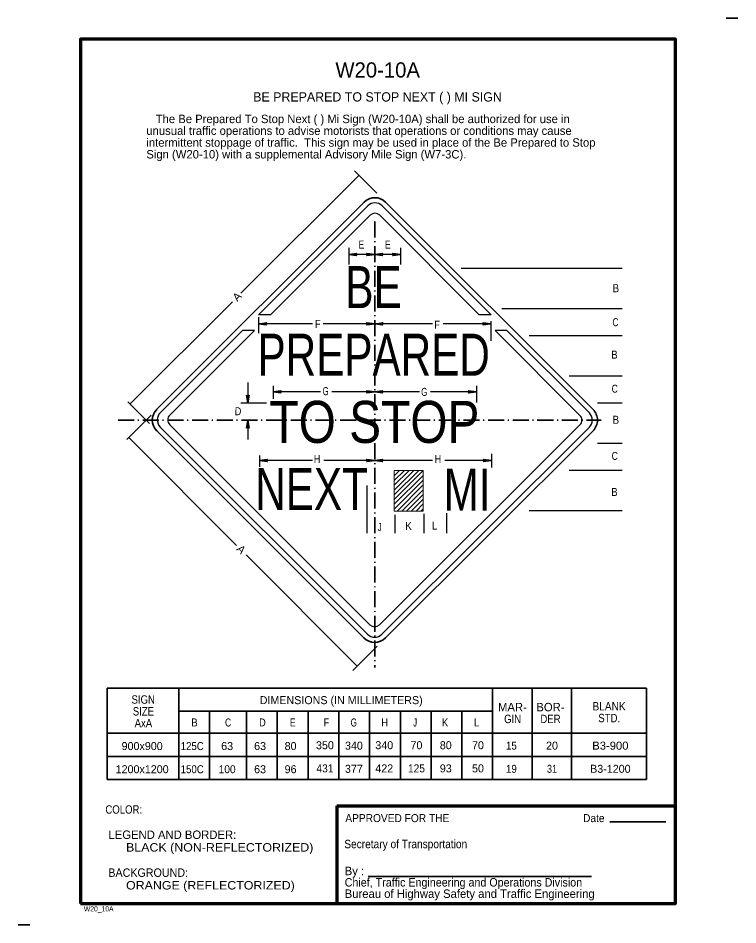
# Model space of a CAD drawing. Extents: x 870593 to 870806, y 249360 to 249629.
import ezdxf
from ezdxf.enums import TextEntityAlignment as Align

# ---------------------------------------------------------------- set-up
doc = ezdxf.new("R2010")
doc.units = 0
doc.header["$LTSCALE"] = 0.95
doc.linetypes.add('DOT_DASHED', pattern=[7.7, 5, -1.2, 0.3, -1.2])
doc.layers.add('1', color=7, linetype='Continuous', lineweight=35)
doc.layers.add('3', color=7, linetype='Continuous', lineweight=25)
doc.layers.add('2', color=7, linetype='Continuous')

msp = doc.modelspace()

# ---------------------------------------------------------------- linework, layer by layer
at = {"layer": '1'}
for p, q in [((870806.1554, 249628.8861), (870802.6554, 249628.8861)), ((870701.6705, 249574.267), (870763.1887, 249512.7487)), ((870633.7721, 249506.4008), (870695.2373, 249444.9356)), ((870768.1554, 249390.3861), (870784.7804, 249390.3861)), ((870696.5304, 249374.1361), (870762.7804, 249374.1361)), ((870596.1554, 249359.7611), (870592.6554, 249359.7611))]:
    msp.add_line(p, q, dxfattribs=at)
at = {"layer": '1', "linetype": 'DOT_DASHED'}
for p, q in [((870698.4193, 249568.5297), (870698.4193, 249436.129)), ((870622.3144, 249509.5669), (870765.6266, 249509.5669))]:
    msp.add_line(p, q, dxfattribs=at)
at = {"layer": '1', "lineweight": 70}
for q in [(870787.6554, 249395.1361), (870687.1554, 249366.1361)]:
    msp.add_line((870687.1554, 249395.1361), q, dxfattribs=at)
msp.add_lwpolyline([(870611.1554, 249366.1361), (870787.6554, 249366.1361), (870787.6554, 249622.6361), (870611.1554, 249622.6361)], close=True, dxfattribs=at)
at = {"layer": '1'}
for centre, start, end in [((870698.4885, 249571.085), 45, 134.93558), ((870760.0068, 249509.5668), 314.93536, 45), ((870698.4193, 249448.1176), 225, 314.93578)]:
    msp.add_arc(centre, 4.5, start, end, dxfattribs=at)
at = {"layer": '3', "lineweight": 35}
for p, q in [((870658.7477, 249547.2164), (870693.7345, 249582.203)), ((870699.0393, 249576.8982), (870692.4095, 249583.528)), ((870633.7721, 249512.8708), (870695.3101, 249574.2706)), ((870656.2165, 249544.6851), (870625.8021, 249514.2707)), ((870631.6121, 249508.5608), (870625.1521, 249515.0207)), ((870632.0821, 249511.0908), (870624.8621, 249503.8708)), ((870701.5976, 249444.932), (870763.1851, 249506.3811)), ((870657.4789, 249472.3499), (870625.4321, 249504.5207)), ((870660.2974, 249469.6239), (870693.2233, 249436.5576)), ((870699.1584, 249442.4928), (870691.9261, 249435.2605)), ((870619.0358, 249430.0185), (870779.0358, 249430.0185)), ((870619.0358, 249430.0185), (870619.0358, 249402.8935)), ((870640.2858, 249430.0185), (870640.2858, 249402.8935)), ((870733.4108, 249430.0185), (870733.4108, 249402.8935)), ((870733.4108, 249430.0185), (870733.4108, 249409.7685)), ((870745.1608, 249430.0185), (870745.1608, 249402.8935)), ((870756.7858, 249430.0185), (870756.7858, 249402.8935)), ((870779.0358, 249430.0185), (870779.0358, 249402.8935)), ((870733.4108, 249423.1435), (870640.2858, 249423.1435)), ((870649.4108, 249423.1435), (870649.4108, 249402.8935)), ((870660.4108, 249423.1435), (870660.4108, 249402.8935)), ((870669.5358, 249423.1435), (870669.5358, 249402.8935)), ((870678.6608, 249423.1435), (870678.6608, 249402.8935)), ((870687.7858, 249423.1435), (870687.7858, 249402.8935)), ((870696.9108, 249423.1435), (870696.9108, 249402.8935)), ((870706.0358, 249423.1435), (870706.0358, 249402.8935)), ((870715.1608, 249423.1435), (870715.1608, 249402.8935)), ((870724.2858, 249423.1435), (870724.2858, 249402.8935)), ((870619.0358, 249416.6435), (870779.0358, 249416.6435)), ((870619.0358, 249409.7685), (870779.0358, 249409.7685)), ((870619.0358, 249409.7685), (870779.0358, 249409.7685)), ((870619.0358, 249402.8935), (870779.0358, 249402.8935))]:
    msp.add_line(p, q, dxfattribs=at)
at = {"layer": '3'}
for p, q in [((870697.0746, 249570.3809), (870667.4804, 249540.8531)), ((870690.7392, 249560.6763), (870690.7392, 249555.7943)), ((870706.0992, 249560.6763), (870706.0992, 249555.7943)), ((870698.4193, 249558.7094), (870690.7392, 249558.7094)), ((870706.0992, 249558.7094), (870698.4193, 249558.7094)), ((870771.8021, 249554.6069), (870724.061, 249554.6069)), ((870771.8021, 249542.6069), (870736.149, 249542.6069)), ((870663.9393, 249540.087), (870663.9393, 249535.4172)), ((870679.9691, 249538.1201), (870663.9393, 249538.1201)), ((870698.4193, 249538.1201), (870683.1316, 249538.1201)), ((870715.5783, 249538.1201), (870698.4193, 249538.1201)), ((870732.8993, 249538.1201), (870718.7593, 249538.1201)), ((870732.8993, 249538.9894), (870732.8993, 249533.0825)), ((870637.6107, 249511.0505), (870662.7484, 249536.1318)), ((870771.8021, 249534.6069), (870744.2076, 249534.6069)), ((870771.8021, 249522.6069), (870756.0835, 249522.6069)), ((870660.7955, 249520.7351), (870660.7955, 249514.6069)), ((870668.2593, 249519.7101), (870668.2593, 249515.8894)), ((870728.5792, 249519.7101), (870728.5792, 249514.8281)), ((870682.3019, 249517.9554), (870668.2593, 249517.9554)), ((870698.4193, 249517.9554), (870685.6764, 249517.9554)), ((870711.761, 249517.9554), (870698.4193, 249517.9554)), ((870728.5792, 249517.9554), (870714.942, 249517.9554)), ((870666.3781, 249514.6069), (870658.7435, 249514.6069)), ((870771.8021, 249514.6069), (870764.5664, 249514.6069)), ((870660.7955, 249509.5669), (870660.7955, 249503.7906)), ((870634.808, 249507.5145), (870696.2979, 249446.0246)), ((870697.006, 249448.8236), (870637.6091, 249508.2205)), ((870759.2969, 249508.1524), (870699.8329, 249448.822)), ((870700.5381, 249446.0223), (870762.0974, 249507.4431)), ((870771.8021, 249502.6069), (870764.5664, 249502.6069)), ((870664.2351, 249499.1209), (870664.2351, 249495.7247)), ((870733.0275, 249499.5455), (870733.0275, 249495.5125)), ((870679.976, 249497.5785), (870664.2351, 249497.5785)), ((870698.4193, 249497.5785), (870683.3438, 249497.5785)), ((870715.5783, 249497.5785), (870698.4193, 249497.5785)), ((870733.0275, 249497.5785), (870719.1834, 249497.5785)), ((870771.8021, 249494.6069), (870756.0835, 249494.6069)), ((870696.0811, 249490.206), (870696.0811, 249475.9846)), ((870712.9684, 249481.735), (870712.9684, 249475.9846)), ((870719.7253, 249481.9474), (870719.7253, 249475.9846)), ((870771.8021, 249482.6069), (870744.2076, 249482.6069)), ((870704.3845, 249481.4166), (870704.3845, 249475.9846))]:
    msp.add_line(p, q, dxfattribs=at)
at = {"layer": '3', "lineweight": 13}
for p, q in [((870704.2325, 249494.4832), (870704.4128, 249494.6635)), ((870704.2325, 249493.069), (870705.827, 249494.6635)), ((870704.2325, 249491.6547), (870707.2412, 249494.6635)), ((870704.2325, 249490.2406), (870708.6554, 249494.6635)), ((870704.2325, 249488.8264), (870710.0696, 249494.6635)), ((870704.2325, 249487.4121), (870711.4839, 249494.6635)), ((870704.2325, 249485.998), (870712.8214, 249494.5869)), ((870704.2325, 249484.5837), (870712.8214, 249493.1726)), ((870704.2325, 249483.1695), (870712.8214, 249491.7584)), ((870705.042, 249482.5648), (870712.8214, 249490.3441)), ((870706.4561, 249482.5648), (870712.8214, 249488.93)), ((870707.8704, 249482.5648), (870712.8214, 249487.5158)), ((870709.2846, 249482.5648), (870712.8214, 249486.1015)), ((870710.6987, 249482.5648), (870712.8214, 249484.6874)), ((870712.113, 249482.5648), (870712.8214, 249483.2731))]:
    msp.add_line(p, q, dxfattribs=at)
at = {"layer": '3'}
for points in [[(870667.4804, 249540.8531), (870663.9694, 249540.8531), (870696.3695, 249573.1805)], [(870700.6098, 249573.1781), (870732.9348, 249540.8531), (870729.4276, 249540.8531), (870699.9015, 249570.3792)], [(870693.0335, 249558.4214), (870692.948, 249558.5875), (870690.7392, 249558.7094), (870693.0335, 249558.4214), (870693.1511, 249558.3208), (870690.7392, 249558.7094), (870692.9463, 249558.8185), (870693.0269, 249558.9829), (870690.7392, 249558.7094), (870693.1511, 249559.0926), (870693.0269, 249558.9829)], [(870696.125, 249558.9974), (870696.2105, 249558.8312), (870698.4193, 249558.7094), (870696.125, 249558.9974), (870696.0074, 249559.098), (870698.4193, 249558.7094), (870696.2122, 249558.6003), (870696.1316, 249558.4359), (870698.4193, 249558.7094), (870696.0074, 249558.3261), (870696.1316, 249558.4359)], [(870700.7135, 249558.4214), (870700.628, 249558.5875), (870698.4193, 249558.7094), (870700.7135, 249558.4214), (870700.8311, 249558.3208), (870698.4193, 249558.7094), (870700.6262, 249558.8185), (870700.7069, 249558.9829), (870698.4193, 249558.7094), (870700.8311, 249559.0926), (870700.7069, 249558.9829)], [(870703.805, 249558.9974), (870703.8905, 249558.8312), (870706.0992, 249558.7094), (870703.805, 249558.9974), (870703.6874, 249559.098), (870706.0992, 249558.7094), (870703.8923, 249558.6003), (870703.8116, 249558.4359), (870706.0992, 249558.7094), (870703.6874, 249558.3261), (870703.8116, 249558.4359)], [(870666.2335, 249537.8321), (870666.148, 249537.9983), (870663.9393, 249538.1201), (870666.2335, 249537.8321), (870666.3511, 249537.7315), (870663.9393, 249538.1201), (870666.1462, 249538.2293), (870666.2269, 249538.3936), (870663.9393, 249538.1201), (870666.3511, 249538.5034), (870666.2269, 249538.3936)], [(870696.125, 249538.4081), (870696.2105, 249538.242), (870698.4193, 249538.1201), (870696.125, 249538.4081), (870696.0074, 249538.5088), (870698.4193, 249538.1201), (870696.2122, 249538.011), (870696.1316, 249537.8466), (870698.4193, 249538.1201), (870696.0074, 249537.7369), (870696.1316, 249537.8466)], [(870700.7135, 249537.8321), (870700.628, 249537.9983), (870698.4193, 249538.1201), (870700.7135, 249537.8321), (870700.8311, 249537.7315), (870698.4193, 249538.1201), (870700.6262, 249538.2293), (870700.7069, 249538.3936), (870698.4193, 249538.1201), (870700.8311, 249538.5034), (870700.7069, 249538.3936)], [(870730.605, 249538.4081), (870730.6905, 249538.242), (870732.8993, 249538.1201), (870730.605, 249538.4081), (870730.4874, 249538.5088), (870732.8993, 249538.1201), (870730.6923, 249538.011), (870730.6116, 249537.8466), (870732.8993, 249538.1201), (870730.4874, 249537.7369), (870730.6116, 249537.8466)], [(870662.7484, 249536.1318), (870659.2375, 249536.1318), (870634.8104, 249511.7595)], [(870762.0998, 249511.6881), (870737.6561, 249536.1318), (870734.149, 249536.1318), (870759.2984, 249510.9824)], [(870661.0835, 249516.9011), (870660.9174, 249516.8156), (870660.7955, 249514.6069), (870661.0835, 249516.9011), (870661.1841, 249517.0187), (870660.7955, 249514.6069), (870660.6864, 249516.8139), (870660.522, 249516.8945), (870660.7955, 249514.6069), (870660.4123, 249517.0187), (870660.522, 249516.8945)], [(870670.5535, 249517.6674), (870670.468, 249517.8335), (870668.2593, 249517.9554), (870670.5535, 249517.6674), (870670.6711, 249517.5667), (870668.2593, 249517.9554), (870670.4663, 249518.0645), (870670.5469, 249518.2289), (870668.2593, 249517.9554), (870670.6711, 249518.3386), (870670.5469, 249518.2289)], [(870696.125, 249518.2434), (870696.2105, 249518.0773), (870698.4193, 249517.9554), (870696.125, 249518.2434), (870696.0074, 249518.344), (870698.4193, 249517.9554), (870696.2122, 249517.8463), (870696.1316, 249517.6819), (870698.4193, 249517.9554), (870696.0074, 249517.5721), (870696.1316, 249517.6819)], [(870700.7135, 249517.6674), (870700.628, 249517.8335), (870698.4193, 249517.9554), (870700.7135, 249517.6674), (870700.8311, 249517.5667), (870698.4193, 249517.9554), (870700.6262, 249518.0645), (870700.7069, 249518.2289), (870698.4193, 249517.9554), (870700.8311, 249518.3386), (870700.7069, 249518.2289)], [(870726.285, 249518.2434), (870726.3705, 249518.0773), (870728.5792, 249517.9554), (870726.285, 249518.2434), (870726.1674, 249518.344), (870728.5792, 249517.9554), (870726.3723, 249517.8463), (870726.2916, 249517.6819), (870728.5792, 249517.9554), (870726.1674, 249517.5721), (870726.2916, 249517.6819)], [(870660.5075, 249507.2726), (870660.6736, 249507.3581), (870660.7955, 249509.5669), (870660.5075, 249507.2726), (870660.4069, 249507.155), (870660.7955, 249509.5669), (870660.9046, 249507.3599), (870661.069, 249507.2793), (870660.7955, 249509.5669), (870661.1787, 249507.155), (870661.069, 249507.2793)], [(870666.5294, 249497.2905), (870666.4439, 249497.4566), (870664.2351, 249497.5785), (870666.5294, 249497.2905), (870666.647, 249497.1899), (870664.2351, 249497.5785), (870666.4421, 249497.6876), (870666.5228, 249497.852), (870664.2351, 249497.5785), (870666.647, 249497.9618), (870666.5228, 249497.852)], [(870696.125, 249497.8665), (870696.2105, 249497.7004), (870698.4193, 249497.5785), (870696.125, 249497.8665), (870696.0074, 249497.9671), (870698.4193, 249497.5785), (870696.2122, 249497.4694), (870696.1316, 249497.305), (870698.4193, 249497.5785), (870696.0074, 249497.1952), (870696.1316, 249497.305)], [(870700.7135, 249497.2905), (870700.628, 249497.4566), (870698.4193, 249497.5785), (870700.7135, 249497.2905), (870700.8311, 249497.1899), (870698.4193, 249497.5785), (870700.6262, 249497.6876), (870700.7069, 249497.852), (870698.4193, 249497.5785), (870700.8311, 249497.9618), (870700.7069, 249497.852)], [(870730.7333, 249497.8665), (870730.8187, 249497.7004), (870733.0275, 249497.5785), (870730.7333, 249497.8665), (870730.6156, 249497.9671), (870733.0275, 249497.5785), (870730.8205, 249497.4694), (870730.7399, 249497.305), (870733.0275, 249497.5785), (870730.6156, 249497.1952), (870730.7399, 249497.305)]]:
    msp.add_lwpolyline(points, dxfattribs=at)
at = {"layer": '3', "lineweight": 13}
msp.add_lwpolyline([(870704.2325, 249494.6635), (870712.8214, 249494.6635), (870712.8214, 249482.5648), (870704.2325, 249482.5648)], close=True, dxfattribs=at)
at = {"layer": '3'}
for centre, radius, start, end in [((870698.4884, 249571.0568), 3, 44.99942, 134.93582), ((870698.4872, 249568.9651), 2, 45, 134.93526), ((870636.9293, 249509.6358), 3, 134.93519, 225), ((870759.9784, 249509.5669), 3, 314.93486, 44.99879), ((870639.0234, 249509.6347), 2, 134.93591, 225), ((870757.8842, 249509.5681), 2, 314.93575, 45), ((870698.4202, 249450.2378), 2, 225, 314.9358), ((870698.4192, 249448.1459), 3, 224.99998, 314.93578)]:
    msp.add_arc(centre, radius, start, end, dxfattribs=at)
at = {"layer": '3', "lineweight": 35}
msp.add_arc((870636.9405, 249509.5916), 4.4999, 135, 225, dxfattribs=at)

# ---------------------------------------------------------------- texts
at = {"layer": '1'}
for s, height, p in [('W20-10A', 4.5, (870699.3091, 249611.2611)), ('BE PREPARED TO STOP NEXT ( ) MI SIGN', 2.75, (870699.2579, 249604.1361))]:
    msp.add_text(s, height=height, dxfattribs=at).set_placement(p, align=Align.CENTER)
for s, height, width, p in [('COLOR:', 2.5, 0.85, (870618.5304, 249392.7605)), ('Secretary of Transportation', 2.5, 0.9, (870689.4054, 249382.5111)), ('      BLACK (NON-REFLECTORIZED)', 2.5, 1.1, (870618.5304, 249381.5113)), (' BACKGROUND:', 2.5, 0.95, (870618.5304, 249374.0118)), ('      ORANGE (REFLECTORIZED)', 2.5, 1.1, (870618.5304, 249370.262)), ('Chief, Traffic Engineering and Operations Division', 2.5, 0.95, (870689.5304, 249371.1361)), ('W20_10A', 1.5, 0.8, (870612.1554, 249363.7611))]:
    msp.add_text(s, height=height, dxfattribs=dict(at, width=width)).set_placement(p)
at = {"layer": '1', "width": 0.95}
for s, p in [('APPROVED FOR THE', (870705.1326, 249390.2611)), ('Date ', (870763.8421, 249390.2611))]:
    msp.add_text(s, height=2.375, dxfattribs=at).set_placement(p, align=Align.CENTER)
at = {"layer": '1'}
for s, p in [(' LEGEND AND BORDER:', (870618.5304, 249385.261)), ('By :', (870689.5304, 249374.5111)), ('Bureau of Highway Safety and Traffic Engineering', (870689.5304, 249367.7611))]:
    msp.add_text(s, height=2.5, dxfattribs=at).set_placement(p)
at = {"layer": '2'}
for s, p in [('   The Be Prepared To Stop Next ( ) Mi Sign (W20-10A) shall be authorized for use in', (870630.6823, 249597.7249)), ('unusual traffic operations to advise motorists that operations or conditions may cause', (870630.6823, 249594.2251)), ('intermittent stoppage of traffic.  This sign may be used in place of the Be Prepared to Stop', (870630.6823, 249590.7254)), ('Sign (W20-10) with a supplemental Advisory Mile Sign (W7-3C).', (870630.6823, 249587.2256))]:
    msp.add_text(s, height=2.5, dxfattribs=at).set_placement(p)
at = {"layer": '3'}
for s, height, width, p in [('E', 2.374, 0.8, (870694.4772, 249560.4974)), ('E', 2.374, 0.8, (870702.3238, 249560.4974)), ('BE', 12.49, 0.75, (870698.0725, 249542.8131)), ('B', 2.374, 0.9, (870769.9741, 249547.5496)), ('F', 2.374, 0.85, (870681.5411, 249536.9366)), ('F', 2.374, 0.85, (870716.9566, 249536.7244)), ('PREPARED', 12.49, 0.75, (870698.1242, 249522.7384)), ('B', 2.374, 0.9, (870769.5499, 249527.8095)), ('G', 2.374, 0.75, (870683.8739, 249516.9843)), ('G', 2.374, 0.75, (870713.1394, 249516.772)), ('TO STOP', 12.49, 0.85, (870698.3488, 249502.8039)), ('B', 2.374, 0.9, (870769.9741, 249508.4939)), ('H', 2.374, 0.85, (870681.3289, 249496.8196)), ('H', 2.374, 0.85, (870717.1687, 249496.8196)), ('NEXT', 12.49, 0.75, (870679.6886, 249482.8876)), ('MI', 12.49, 0.75, (870725.8349, 249482.6754)), ('B', 2.374, 0.9, (870769.5499, 249487.0556)), ('J', 2.374, 0.65, (870699.8851, 249476.6549)), ('K', 2.374, 0.9, (870708.474, 249476.9734)), ('L', 2.374, 0.9, (870716.2144, 249477.0795)), ('SIGN', 2.5, 0.85, (870629.7588, 249425.3935)), ('BLANK', 2.5, 0.9, (870767.9461, 249423.3935)), ('SIZE', 2.5, 0.85, (870629.8218, 249421.8935)), ('STD.', 2.5, 0.85, (870767.9959, 249419.8935)), ('AxA', 2.5, 0.85, (870629.8146, 249418.3935)), ('B', 2.375, 0.9, (870644.9584, 249418.6435)), ('C', 2.375, 0.8, (870654.9354, 249418.6435)), ('D', 2.375, 0.85, (870665.1284, 249418.6435)), ('E', 2.375, 0.8, (870674.1264, 249418.6435)), ('F', 2.375, 0.85, (870684.0958, 249418.6435)), ('G', 2.375, 0.75, (870692.2052, 249418.6435)), ('H', 2.375, 0.85, (870701.3716, 249418.6435)), ('J', 2.375, 0.65, (870710.4321, 249418.6435)), ('K', 2.375, 0.9, (870719.2991, 249418.6435)), ('L', 2.375, 0.9, (870728.6379, 249418.6435)), ('GIN', 2.5, 0.85, (870739.3422, 249419.6435)), ('DER', 2.5, 0.85, (870750.5752, 249419.6435)), ('125C', 2.375, 0.9, (870644.2993, 249411.6435)), ('15', 2.375, 0.9, (870738.9799, 249411.7685)), ('B3-900', 2.375, 1.05, (870768.3357, 249411.7685)), ('150C', 2.375, 0.9, (870644.2993, 249404.7685)), ('100', 2.375, 0.95, (870654.6516, 249404.7685)), ('431', 2.375, 0.95, (870683.6654, 249405.0185)), ('125', 2.375, 0.95, (870710.812, 249405.0185)), ('19', 2.375, 0.9, (870738.9799, 249404.8935)), ('31', 2.375, 0.85, (870751.023, 249404.8935))]:
    msp.add_text(s, height=height, dxfattribs=dict(at, width=width)).set_placement(p, align=Align.CENTER)
for height, rotation, p in [(2.375, 45, (870658.4264, 249545.3861)), (2.374, 315, (870657.9874, 249470.3644))]:
    msp.add_text('A', height=height, rotation=rotation, dxfattribs=at).set_placement(p, align=Align.CENTER)
for s, width, p in [('C', 0.8, (870769.8338, 249537.4544)), ('C', 0.8, (870769.6217, 249517.7143)), ('D', 0.85, (870657.8613, 249511.0194)), ('C', 0.8, (870769.6217, 249497.7619))]:
    msp.add_text(s, height=2.374, rotation=359, dxfattribs=dict(at, width=width)).set_placement(p, align=Align.CENTER)
for s, height, p in [('DIMENSIONS (IN MILLIMETERS)', 2.375, (870688.4867, 249425.2685)), ('MAR-', 2.5, (870739.2796, 249423.1435)), ('BOR-', 2.5, (870750.5599, 249423.1435)), ('350', 2.375, (870683.6655, 249411.8935)), ('340', 2.375, (870701.2594, 249411.8935)), ('70', 2.375, (870710.8119, 249411.8935)), ('80', 2.375, (870719.5093, 249411.8935)), ('70', 2.375, (870729.0619, 249411.8935)), ('900x900', 2.375, (870629.4395, 249411.6435)), ('63', 2.375, (870654.6517, 249411.6435)), ('63', 2.375, (870664.4243, 249411.6435)), ('80', 2.375, (870673.4754, 249411.6435)), ('340', 2.375, (870692.2595, 249411.7685)), ('20', 2.375, (870751.0229, 249411.7685)), ('1200x1200', 2.375, (870629.4394, 249404.7685)), ('63', 2.375, (870664.4243, 249404.7685)), ('96', 2.375, (870673.4755, 249404.7685)), ('377', 2.375, (870692.2594, 249404.8935)), ('422', 2.375, (870701.2594, 249405.0185)), ('93', 2.375, (870719.5094, 249405.0185)), ('50', 2.375, (870729.0619, 249405.0185)), ('B3-1200', 2.375, (870768.3357, 249404.8935))]:
    msp.add_text(s, height=height, dxfattribs=at).set_placement(p, align=Align.CENTER)

doc.saveas('drawing.dxf')
